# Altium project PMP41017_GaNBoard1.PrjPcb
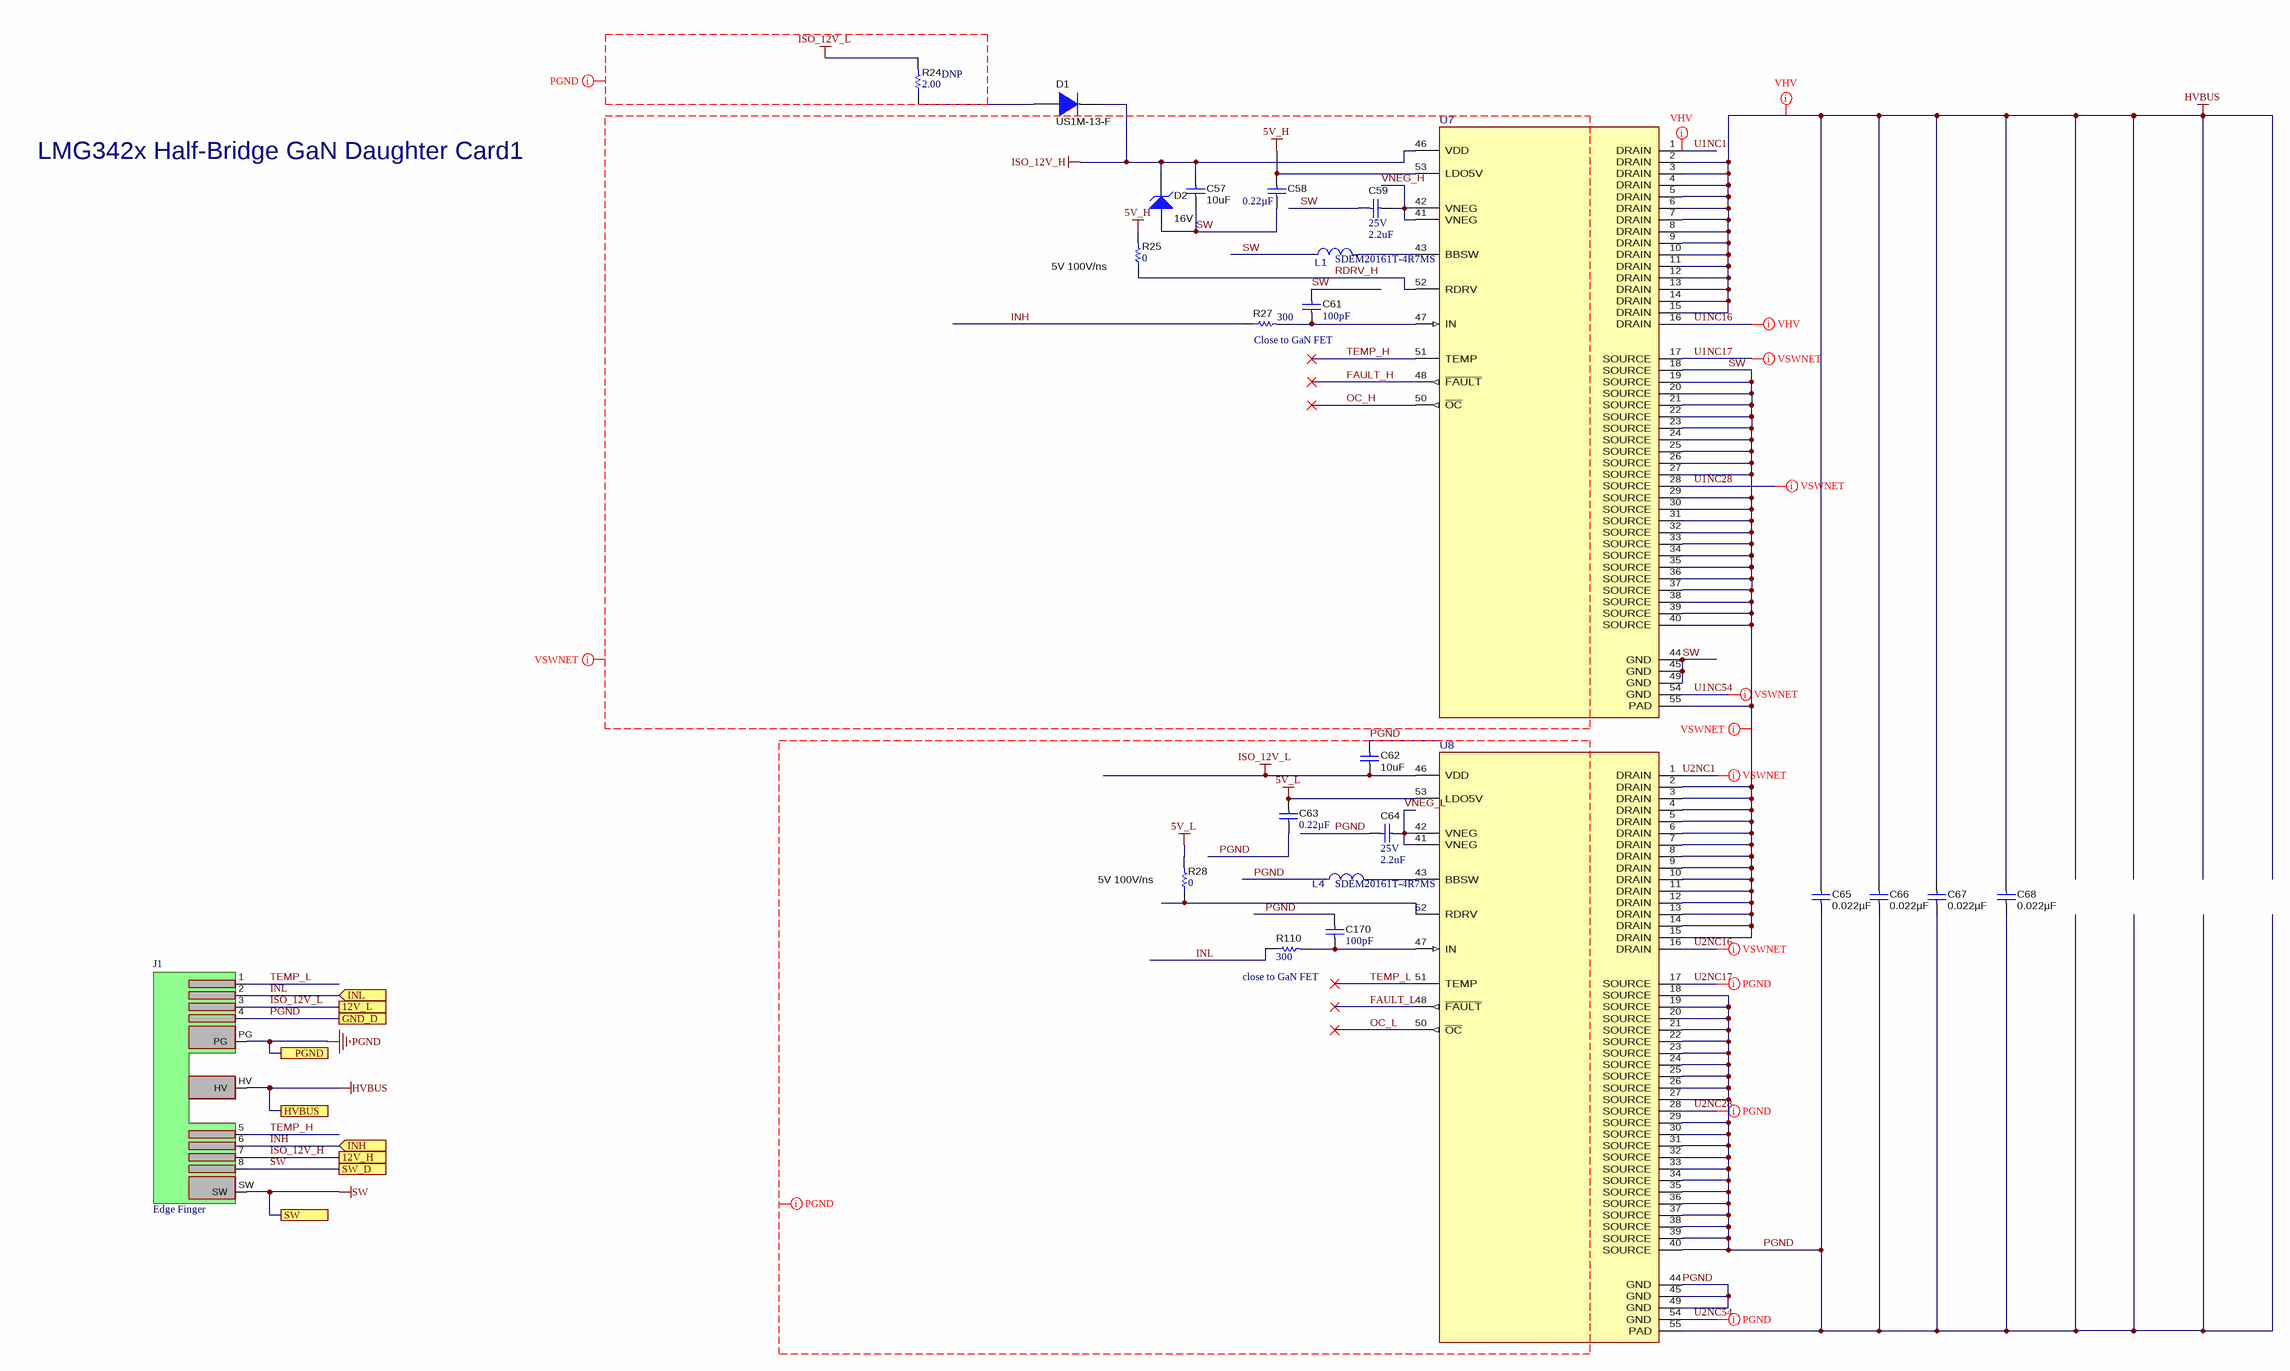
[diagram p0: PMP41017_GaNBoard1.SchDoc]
CopyrightYear: 2018; PCB_Layout: Who did the Layout?; PCB_Rev: E1; PRJ_Customer: Public Release; PRJ_Engineer: Enter name of project lead; PRJ_Number: XXX###; PRJ_Title: Change in menu Project|Project Options|Parameters; SCH_Rev: E1; TechSupport: http://www.ti.com/support; TID: N/A
1 sheet, 24 parts. Net scope: flat (ports and power ports of the same name join across sheets).
Board file: PMP41017_GaNBoard1.PcbDoc

## Sheet PMP41017_GaNBoard1.SchDoc
size A2; Date: Not shown in title block; ApprovedBy: Not shown in title block; CheckedBy: Not shown in title block; Author: Not shown in title block; CompanyName: Not shown in title block; Engineer: Not shown in title block; Organization: Not shown in title block; Address1: Not shown in title block; Address2: Not shown in title block; Address3: Not shown in title block; Address4: Not shown in title block; DocumentNumber: 1; Revision: Use project parameter SCH_Rev; SheetNumber: 2; SheetTotal: 2; PageSetup: Record=PageOptions¦CenterHorizontal=True¦CenterVertical=True¦PrintScale=0.69¦XCorrection=1.00¦YCorrection=1.00¦PrintKind=0¦BorderSize=5000000¦LeftOffset=0¦BottomOffset=0¦Orientation=2¦PaperLength=1000¦PaperWidth=1000¦Scale=100¦PaperSource=15¦PrintQuality=600¦MediaType=1¦DitherType=10¦PaperKind=Letter¦PrintScaleMode=1

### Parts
C57  ValueDisplayed: 10uF  [1206_190]  (hidden comment: C1206C106K3RACTU)
C58  ValueDisplayed: 0.22µF  [0402]  (hidden comment: CL05B224KO5NNNC)
C59  VDC_V: 25V  ValueDisplayed: 2.2uF  [0805_HV]  (hidden comment: GRM219R61E225KA12D)
C61  ValueDisplayed: 100pF  [0402]  (hidden comment: 885012205055)
C62  ValueDisplayed: 10uF  [1206_190]  (hidden comment: C1206C106K3RACTU)
C63  ValueDisplayed: 0.22µF  [0402]  (hidden comment: CL05B224KO5NNNC)
C64  VDC_V: 25V  ValueDisplayed: 2.2uF  [0805_HV]  (hidden comment: GRM219R61E225KA12D)
C65  ValueDisplayed: 0.022µF  [1206_190]  (hidden comment: C1206C223KDRACTU)
C66  ValueDisplayed: 0.022µF  [1206_190]  (hidden comment: C1206C223KDRACTU)
C67  ValueDisplayed: 0.022µF  [1206_190]  (hidden comment: C1206C223KDRACTU)
C68  ValueDisplayed: 0.022µF  [1206_190]  (hidden comment: C1206C223KDRACTU)
C170  ValueDisplayed: 100pF  [0402]  (hidden comment: 885012205055)
D1  US1M-13-F  [SMA]
D2  value 16V  [SOD-123]  (hidden comment: BZT52C16-7-F)
J1  Edge Finger  [EC_GaN_DC_HBLLC]  (no BOM)
L1  SDEM20161T-4R7MS  [FP-SDEM20161T-4R7MS_SMD2-MFG]  (value not drawn)
L4  SDEM20161T-4R7MS  [FP-SDEM20161T-4R7MS_SMD2-MFG]  (value not drawn)
R24  ValueDisplayed: 2.00  [0603]  (hidden comment: MCT06030C2008FP500)
R25  ValueDisplayed: 0  [0402]  (hidden comment: MCR01MZPJ000)
R27  ValueDisplayed: 300  [0402]  (hidden comment: CRCW0402300RJNED)
R28  ValueDisplayed: 0  [0402]  (hidden comment: MCR01MZPJ000)
R110  ValueDisplayed: 300  [0402]  (hidden comment: CRCW0402300RJNED)
U7  LMG3422R030RQZT  [RQZ0054A-MFG-NV]  (value not drawn)
U8  LMG3422R030RQZT  [RQZ0054A-MFG-NV]  (value not drawn)

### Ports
12V_H, 12V_L, GND_D, HVBUS, INH (in), INL (in), PGND, SW, SW_D

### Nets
5V_H: C58.1 R25.2 U7.53(LDO5V)
5V_L: C63.1 R28.2 U8.53(LDO5V)
HVBUS: C65.1 C66.1 C67.1 C68.1 J1.HV U7.2(DRAIN) U7.3(DRAIN) U7.4(DRAIN) U7.5(DRAIN) U7.6(DRAIN) U7.7(DRAIN) U7.8(DRAIN) U7.9(DRAIN) U7.10(DRAIN) U7.11(DRAIN) U7.12(DRAIN) U7.13(DRAIN) U7.14(DRAIN) U7.15(DRAIN) ; port HVBUS
ISO_12V_H: C57.1 D1.1(K) D2.1(K) J1.7 U7.46(VDD) ; port 12V_H
ISO_12V_L: C62.2 J1.3 R24.2 U8.46(VDD) ; port 12V_L
PGND: C62.1 C63.2 C64.2 C65.2 C66.2 C67.2 C68.2 C170.1 J1.4 J1.PG L4.1 U8.18(SOURCE) U8.19(SOURCE) U8.20(SOURCE) U8.21(SOURCE) U8.22(SOURCE) U8.23(SOURCE) U8.24(SOURCE) U8.25(SOURCE) U8.26(SOURCE) U8.27(SOURCE) U8.29(SOURCE) U8.30(SOURCE) U8.31(SOURCE) U8.32(SOURCE) U8.33(SOURCE) U8.34(SOURCE) U8.35(SOURCE) U8.36(SOURCE) U8.37(SOURCE) U8.38(SOURCE) U8.39(SOURCE) U8.40(SOURCE) U8.44(GND) U8.45(GND) U8.49(GND) U8.55(PAD) ; port GND_D, port PGND
SW: C57.2 C58.2 C59.2 C61.1 D2.2(A) J1.8 J1.SW L1.1 U7.18(SOURCE) U7.19(SOURCE) U7.20(SOURCE) U7.21(SOURCE) U7.22(SOURCE) U7.23(SOURCE) U7.24(SOURCE) U7.25(SOURCE) U7.26(SOURCE) U7.27(SOURCE) U7.29(SOURCE) U7.30(SOURCE) U7.31(SOURCE) U7.32(SOURCE) U7.33(SOURCE) U7.34(SOURCE) U7.35(SOURCE) U7.36(SOURCE) U7.37(SOURCE) U7.38(SOURCE) U7.39(SOURCE) U7.40(SOURCE) U7.44(GND) U7.45(GND) U7.49(GND) U7.55(PAD) U8.2(DRAIN) U8.3(DRAIN) U8.4(DRAIN) U8.5(DRAIN) U8.6(DRAIN) U8.7(DRAIN) U8.8(DRAIN) U8.9(DRAIN) U8.10(DRAIN) U8.11(DRAIN) U8.12(DRAIN) U8.13(DRAIN) U8.14(DRAIN) U8.15(DRAIN) ; port SW, port SW_D
FAULT_H: U7.48(~{FAULT})
FAULT_L: U8.48(~{FAULT})
INH: J1.6 R27.1 ; port INH
INL: J1.2 R110.1 ; port INL
OC_H: U7.50(~{OC})
OC_L: U8.50(~{OC})
RDRV_H: R25.1 U7.52(RDRV)
TEMP_H: J1.5 U7.51(TEMP)
TEMP_L: J1.1 U8.51(TEMP)
U1NC1: U7.1(DRAIN)
U1NC16: U7.16(DRAIN)
U1NC17: U7.17(SOURCE)
U1NC28: U7.28(SOURCE)
U1NC54: U7.54(GND)
U2NC1: U8.1(DRAIN)
U2NC16: U8.16(DRAIN)
U2NC17: U8.17(SOURCE)
U2NC28: U8.28(SOURCE)
U2NC54: U8.54(GND)
VNEG_H: C59.1 U7.41(VNEG) U7.42(VNEG)
VNEG_L: C64.1 U8.41(VNEG) U8.42(VNEG)
NetC61_2: C61.2 R27.2 U7.47(IN)
NetC170_2: C170.2 R110.2 U8.47(IN)
NetD1_2: D1.2(A) R24.1
NetL1_2: L1.2 U7.43(BBSW)
NetL4_2: L4.2 U8.43(BBSW)
NetR28_1: R28.1 U8.52(RDRV)

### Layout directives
net class VSWNET: 5V_H, FAULT_H, INH, ISO_12V_H, OC_H, RDRV_H, SW, TEMP_H, U1NC17, U1NC28, U1NC54, U2NC1, U2NC16, VNEG_H
net class VHV: HVBUS, U1NC1, U1NC16
net class PGND: 5V_L, FAULT_L, INL, ISO_12V_L, OC_L, PGND, TEMP_L, U2NC17, U2NC28, U2NC54, VNEG_L

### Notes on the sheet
- (near R24) DNP
- LMG342x Half-Bridge GaN Daughter Card1
- (near R25) 5V 100V/ns
- (near L1) SDEM20161T-4R7MS
- (near R27) Close to GaN FET
- (near R28) 5V 100V/ns
- (near L4) SDEM20161T-4R7MS
- close to GaN FET

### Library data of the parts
C57 C62 = CMP-0008589-2: CAP, CERM, 10 uF, 25 V, +/- 10%, X7R, 1206_190; Manufacturer: Kemet; Polarized: N; Value: 10uF; U/M: EA; Cap_F: 10µF; Value1: Unknown; VDC_V: 25V; TaMin_C: -55°C; TaMax_C: 125°C; Cap_Case: 1206; SizeArea_mm2: 5.12; SizeAreaWB_mm2: 10.92; SizeX_mm: 3.2; SizeY_mm: 1.6; SizeZ_mm: 1.9; AEC Category: Q200
C58 C63 = CMP-0860563-1: CAP, CERM, 0.22 µF, 16 V,+/- 10%, X7R, 0402; Manufacturer: Samsung Electro-Mechanics; SizeX_mm: 1; Green_REACh: Incomplete; TaMin_C: -55°C; SizeArea_mm2: 0.5; TaMax_C: 125°C; U/M: EA; Green_Lifecycle: Active; SizeAreaWB_mm2: 3; VDC_V: 16V; AEC Qualified: N; SizeZ_mm: 0.6; AEC Category: Q200; Cap_F: 220nF; Value: 0.22uF
C59 C64 = CMP-0008208-1: CAP, CERM, 2.2 uF, 25 V, +/- 10%, X5R, 0805; Manufacturer: MuRata; TaMin_C: -55°C; ESR_ohm: 6m; Polarized: N; SizeAreaWB_mm2: 6.75; Value1: 0.006 ohm; U/M: EA; Value: 2.2uF; TaMax_C: 85°C; SizeZ_mm: 1.45; SizeX_mm: 2; SizeY_mm: 1.25; Cap_Case: 0805; SizeArea_mm2: 2.5; Cap_F: 2.2µF; AEC Category: Q200
C61 C170 = CMP-0006230-2: CAP, CERM, 100 pF, 50 V, +/- 10%, X7R, 0402; Manufacturer: Wurth Elektronik; Polarized: N; Value: 100pF; U/M: EA; Value1: Unknown; VDC_V: 50V; TaMin_C: -55°C; TaMax_C: 125°C; AEC Category: Q200; SizeArea_mm2: 0.5; SizeAreaWB_mm2: 3; SizeX_mm: 1; SizeZ_mm: 0.6
C65-C68 = CMP-0084048-1: CAP, CERM, 0.022 µF, 1000 V,+/- 10%, X7R, AEC-Q200 Grade 1, 1206; Manufacturer: Kemet; Polarized: N; CompType: Capacitor; Value: 0.022uF; U/M: EA; Cap_F: 22nF; VDC_V: 1kV; Value2: 1000V; TaMin_C: -55°C; TaMax_C: 125°C; Cap_Case: 1206; SizeArea_mm2: 5.12; SizeAreaWB_mm2: 10.92; SizeX_mm: 3.2; SizeY_mm: 1.6; SizeZ_mm: 1.9; AEC Category: Q200; AEC Qualified: Y; AEC Grade: 1
D1 = CMP-0076882-1: Diode, Ultrafast, 1000 V, 1 A, SMA; Manufacturer: Diodes Inc.; SizeAreaWB_mm2: 37.3428; Vr_V: 1kV; SizeArea_mm2: 16.3228; TJmax_C: 150°C; AEC Category: Q101; Value: 1000V; SizeZ_mm: 2.87; Green_REACh: Incomplete; Io_A: 1A; Vf_V: 1.7V; SizeY_mm: 2.92; Green_Lifecycle: Not Set; U/M: EA; SizeX_mm: 5.59; RJC_CperW: 30.0
D2 = CMP-0005769-2: Diode, Zener, 16 V, 500 mW, AEC-Q101, SOD-123; Manufacturer: Diodes Inc.; Power_W: 500mW; SizeAreaWB_mm2: 13.095; Value1: 0.5W; RJA_CperW: 338; U/M: EA; SizeZ_mm: 1.35; SizeX_mm: 3.85; SizeY_mm: 1.7; SizeArea_mm2: 6.545; AEC Qualified: Y; AEC Category: Q101
J1 = EC_GaN
L1 L4 = CMP-0089347-1: 4.7µH Unshielded Inductor 1.1A 426mOhm Max 0806 (2016 Metric); Manufacturer: Cyntec; AEC Qualified: No; Material: Metal Dust; Isat: 1.26A; Test Frequency: 1MHz; DCR_ohm: 0.426; SizeZ_mm: 1mm; Tolerance_%: 20%
R24 = CMP-0022732-2: RES, 2.00, 1%, 0.125 W, 0603; Manufacturer: Vishay/Beyschlag; Power_W: 125mW; TempCo: 50 ppm/C; Value_Code: 2R00; U/M: EA; Value: 2.00; EIA_Code: E96; Res_ohm: 2; SizeX_mm: 1.6; SizeY_mm: 0.8; Value2: 0.125W; SizeArea_mm2: 1.28; AEC Qualified: N; AEC Category: Q200; SizeZ_mm: 1
R25 R28 = CMP-0027002-2: RES, 0, 5%, 0.063 W, 0402; Manufacturer: Rohm; Power_W: 63mW; TempCo: 500 ppm/C; Value_Code: 0000; U/M: EA; Value: 0; EIA_Code: E24; SizeX_mm: 1; SizeY_mm: 0.5; SizeZ_mm: 0.6; Value2: 0.063W; VDC_V: 50V; AEC Category: Q200
R27 R110 = CMP-0026902-3: RES, 300, 5%, 0.063 W, AEC-Q200 Grade 0, 0402; Manufacturer: Vishay-Dale; Power_W: 63mW; TempCo: 200 ppm/C; Value_Code: 300R; Value: 300; EIA_Code: E24; SizeX_mm: 1; SizeY_mm: 0.5; SizeZ_mm: 0.6; Value2: 0.063W; AEC Qualified: Y; VDC_V: 50V; AEC Category: Q200; AEC Grade: 0
U7 U8 = CMP-0088545-3: 600-V 30-mΩ Integrated GaN Power Stage with Smart Driver; Manufacturer: Texas Instruments; Standoff Height: 0mm; TJmax_C: +125°C; Number Of Outputs: 1; Nominal Supply Current: 13mA; Max Supply Voltage: 18V; Min Supply Voltage: 7.5V; SizeZ_mm: 0.9mm; Output Voltage: 480V; AEC Qualified: No; AEC Category: Q200; CompType: IC

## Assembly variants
001: not fitted FID1 FID2 FID3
